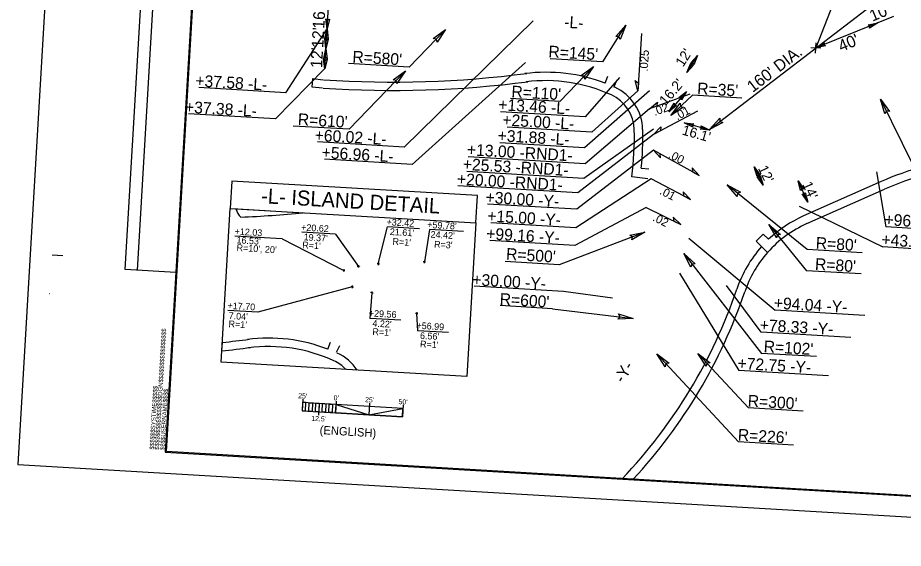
# Model space of a CAD drawing. Extents: x 2011491 to 2012372, y 444688 to 445287.
# Drawn here: x 2011491 to 2012020, y 444688 to 445005 of the extents above; entities that cross this region are included whole.
import ezdxf

# ---------------------------------------------------------------- set-up
doc = ezdxf.new("R2010")
doc.units = 0
for name, color, linetype in [('Old_Level_1', 7, 'Continuous'), ('Old_Level_10', 7, 'Continuous'), ('Prop Conc 5in Monolithic Keyed In Island', 7, 'Continuous'), ('Prop Dimension', 7, 'Continuous'), ('Prop Dimension Text', 7, 'Continuous'), ('Prop PHM English Scale CELL', 7, 'Continuous'), ('Prop Shade Medium', 7, 'Continuous'), ('Prop Superelevation  Arrow CELL', 7, 'Continuous'), ('Prop Superelevation Label', 7, 'Continuous'), ('Prop Terminator CELL', 7, 'Continuous'), ('Sheet Block Revision CELL', 7, 'Continuous'), ('Sheet Block System Information CELL', 7, 'Continuous'), ('Sheet Clip Boundary CELL', 7, 'Continuous'), ('Sheet Plan And Profile CELL', 7, 'Continuous'), ('Sheet Plot Border Outside CELL', 7, 'Continuous')]:
    doc.layers.add(name, color=color, linetype=linetype)

msp = doc.modelspace()

# ---------------------------------------------------------------- linework, layer by layer
at = {"layer": 'Old_Level_1'}
for points in [[(2011617.92, 444891.33), (2011764.48, 444882.69), (2011765.45, 444899.02), (2011618.88, 444907.66)], [(2011617.92, 444891.33), (2011764.48, 444882.69), (2011759.08, 444790.99), (2011612.52, 444799.63)]]:
    msp.add_lwpolyline(points, close=True, dxfattribs=at)
at = {"layer": 'Prop Conc 5in Monolithic Keyed In Island'}
msp.add_arc((2011549.01, 445418.55), 579.25, 266.1491, 266.16124, dxfattribs=at)
at = {"layer": 'Prop Dimension'}
for p, q in [((2011996.65, 445061.65), (2011967.46, 444987.16)), ((2011903.98, 444938.48), (2012030.95, 445035.85)), ((2011675.75, 444998.63), (2011676.73, 445015.19)), ((2012013.8, 445005.94), (2012004.54, 445002.19)), ((2011798.68, 445003.43), (2011721.67, 444928.02)), ((2011840.43, 444978.9), (2011854.11, 445000.81)), ((2012004.54, 445002.19), (2011967.46, 444987.16)), ((2011651.03, 444960.47), (2011675.75, 444998.63)), ((2011675.04, 444986.65), (2011675.75, 444998.63)), ((2011746.5, 444998.19), (2011724.82, 444975.71)), ((2011967.29, 444984.17), (2011967.64, 444990.16)), ((2011674.34, 444974.67), (2011675.04, 444986.65)), ((2011970.46, 444986.99), (2011964.47, 444987.34)), ((2011840.43, 444978.9), (2011808.95, 444980.75)), ((2011890.53, 444972.51), (2011896.92, 444982.66)), ((2011674.14, 444974.68), (2011644.84, 444944.79)), ((2011724.82, 444975.71), (2011688.49, 444977.85)), ((2011794.15, 444978.45), (2011726.51, 444917.66)), ((2011834.76, 444976.08), (2011814.64, 444955.22)), ((2011722.49, 444973.49), (2011688.82, 444938.59)), ((2011850.22, 444969.6), (2011829.74, 444946.05)), ((2011651.03, 444960.47), (2011599.09, 444963.53)), ((2011868.19, 444961.53), (2011829.33, 444927.55)), ((2011861.31, 444961.57), (2011833.82, 444936.82)), ((2011890.38, 444961.28), (2011879.81, 444948.99)), ((2011880.92, 444946.77), (2011893.91, 444958.96)), ((2011923.37, 444957.23), (2011893.91, 444958.96)), ((2011814.64, 444955.22), (2011785.17, 444956.96)), ((2012006.14, 444956.68), (2012035.03, 444897.56)), ((2011644.84, 444944.79), (2011592.9, 444947.85)), ((2011829.74, 444946.05), (2011779.22, 444949.03)), ((2011868.12, 444950.82), (2011829.79, 444918.06)), ((2011904.31, 444938.05), (2011888.8, 444942.42)), ((2011688.82, 444938.59), (2011655.42, 444940.56)), ((2011833.82, 444936.82), (2011783.31, 444939.8)), ((2011870.62, 444938.63), (2011829, 444909.26)), ((2011870.67, 444935.45), (2011825.4, 444900.72)), ((2011721.67, 444928.02), (2011670.02, 444931.06)), ((2011829.33, 444927.55), (2011778.81, 444930.53)), ((2011870.53, 444926.22), (2011824.82, 444890.83)), ((2011829.79, 444918.06), (2011760.01, 444922.17)), ((2011726.51, 444917.66), (2011674.18, 444920.74)), ((2011930.73, 444916.1), (2011936.05, 444905.34)), ((2011829, 444909.26), (2011759.22, 444913.37)), ((2012003.79, 444913.3), (2012009.29, 444880.37)), ((2011869.14, 444909.05), (2011824.17, 444879.83)), ((2011962.39, 444866.78), (2011914.5, 444905.43)), ((2011962.66, 444895.05), (2011956.98, 444907.85)), ((2011825.4, 444900.72), (2011753.72, 444904.94)), ((2011824.82, 444890.83), (2011771.59, 444893.97)), ((2011866.25, 444891.98), (2011823.55, 444869.21)), ((2011957.54, 444892.79), (2012007.49, 444868.35)), ((2011706.31, 444858.22), (2011711.7, 444880.35)), ((2011730.83, 444879.22), (2011711.7, 444880.35)), ((2011736.82, 444878.7), (2011733.79, 444859.42)), ((2011757.08, 444877.51), (2011736.82, 444878.7)), ((2011824.17, 444879.83), (2011773.51, 444882.82)), ((2011939.51, 444881.73), (2011961.92, 444854.17)), ((2012080.44, 444876.17), (2012009.29, 444880.37)), ((2011648.82, 444873.17), (2011620.69, 444874.83)), ((2011680.8, 444875.96), (2011660.71, 444877.14)), ((2011680.8, 444875.96), (2011694.39, 444856.73)), ((2011865.49, 444877.22), (2011814.3, 444857.74)), ((2011891.74, 444873.57), (2011943.2, 444830.62)), ((2011648.82, 444873.17), (2011685.66, 444854.35)), ((2011823.55, 444869.21), (2011772.88, 444872.19)), ((2012061.63, 444865.15), (2012007.49, 444868.35)), ((2011888.63, 444864.37), (2011935.15, 444804.76)), ((2011995.08, 444864.86), (2011962.39, 444866.78)), ((2011814.3, 444857.74), (2011782.01, 444859.64)), ((2011886.03, 444852.69), (2011921.55, 444794.61)), ((2011994.61, 444852.24), (2011961.92, 444854.17)), ((2011690.76, 444844.55), (2011634.44, 444829.39)), ((2011816.92, 444841.71), (2011763.49, 444844.86)), ((2011846.14, 444837.85), (2011816.92, 444841.71)), ((2011934.79, 444817.44), (2011914.18, 444845.27)), ((2011702.44, 444841.03), (2011701.2, 444825.7)), ((2011810.36, 444831.48), (2011779.09, 444833.32)), ((2011810.36, 444831.48), (2011858.52, 444825.7)), ((2011634.44, 444829.39), (2011616.47, 444830.45)), ((2011719.82, 444824.6), (2011701.2, 444825.7)), ((2011729.18, 444828.66), (2011729.62, 444818.35)), ((2011996.74, 444827.46), (2011943.2, 444830.62)), ((2011748.24, 444817.25), (2011729.62, 444818.35)), ((2011988.33, 444814.29), (2011934.79, 444817.44)), ((2011927.3, 444772.21), (2011897.1, 444804.77)), ((2011967.84, 444802.83), (2011935.15, 444804.76)), ((2011921.39, 444751.9), (2011872.61, 444804.48)), ((2011975.09, 444791.45), (2011921.55, 444794.61)), ((2011959.99, 444770.29), (2011927.3, 444772.21)), ((2011954.08, 444749.97), (2011921.39, 444751.9))]:
    msp.add_line(p, q, dxfattribs=at)
at = {"layer": 'Prop Dimension Text'}
for p, q in [((2011694.43, 444857.48), (2011694.35, 444855.98)), ((2011706.31, 444858.22), (2011705.56, 444858.27)), ((2011706.35, 444858.97), (2011706.26, 444857.47)), ((2011706.31, 444858.22), (2011707.05, 444858.18)), ((2011733.79, 444859.42), (2011733.04, 444859.46)), ((2011733.83, 444860.17), (2011733.74, 444858.67)), ((2011733.79, 444859.42), (2011734.54, 444859.38)), ((2011685.66, 444854.35), (2011684.91, 444854.4)), ((2011685.71, 444855.1), (2011685.62, 444853.6)), ((2011685.66, 444854.35), (2011686.41, 444854.31)), ((2011694.39, 444856.73), (2011693.64, 444856.77)), ((2011694.39, 444856.73), (2011695.14, 444856.68)), ((2011690.76, 444844.55), (2011690.01, 444844.59)), ((2011690.8, 444845.3), (2011690.71, 444843.8)), ((2011690.76, 444844.55), (2011691.5, 444844.5)), ((2011702.48, 444841.78), (2011702.39, 444840.28)), ((2011702.44, 444841.03), (2011701.69, 444841.08)), ((2011702.44, 444841.03), (2011703.19, 444840.99)), ((2011729.18, 444828.66), (2011728.43, 444828.7)), ((2011729.23, 444829.41), (2011729.14, 444827.91)), ((2011729.18, 444828.66), (2011729.93, 444828.61))]:
    msp.add_line(p, q, dxfattribs=at)
at = {"layer": 'Prop PHM English Scale CELL'}
for p, q in [((2011661.21, 444777.5), (2011660.8, 444770.51)), ((2011661.09, 444775.5), (2011660.8, 444770.51)), ((2011720.99, 444771.97), (2011661.09, 444775.5)), ((2011661.23, 444777.9), (2011661.23, 444777.9)), ((2011671.08, 444774.91), (2011670.66, 444767.92)), ((2011681.18, 444776.32), (2011680.76, 444769.29)), ((2011701.14, 444775.14), (2011700.73, 444768.15)), ((2011701.16, 444775.54), (2011701.16, 444775.54)), ((2011721.11, 444773.97), (2011720.69, 444766.98)), ((2011721.13, 444774.36), (2011721.13, 444774.36)), ((2011660.8, 444770.51), (2011720.69, 444766.98)), ((2011720.69, 444766.98), (2011720.99, 444771.97))]:
    msp.add_line(p, q, dxfattribs=at)
for points in [[(2011663.09, 444775.38), (2011661.09, 444775.5), (2011660.8, 444770.51), (2011662.8, 444770.39)], [(2011665.09, 444775.26), (2011667.08, 444775.15), (2011666.79, 444770.16), (2011664.79, 444770.27)], [(2011669.08, 444775.03), (2011671.08, 444774.91), (2011670.78, 444769.92), (2011668.78, 444770.04)], [(2011673.07, 444774.79), (2011675.07, 444774.68), (2011674.77, 444769.68), (2011672.78, 444769.8)], [(2011677.07, 444774.56), (2011679.06, 444774.44), (2011678.77, 444769.45), (2011676.77, 444769.57)], [(2011681.06, 444774.32), (2011700.73, 444768.11), (2011680.76, 444769.29)], [(2011700.73, 444768.11), (2011720.88, 444771.89), (2011720.69, 444766.98)]]:
    msp.add_lwpolyline(points, close=True, dxfattribs=at)
at = {"layer": 'Prop Shade Medium'}
for p, q in [((2011666.83, 444963.86), (2011667.18, 444968.85)), ((2011667.18, 444968.85), (2011673.48, 444968.21)), ((2011841.78, 444966.11), (2011843.39, 444970.32)), ((2011672.98, 444963.24), (2011666.83, 444963.86)), ((2011848.75, 444968.02), (2011846.83, 444964)), ((2011863.3, 444915.44), (2011867.78, 444915.01)), ((2011867.12, 444909.05), (2011857.7, 444910.24)), ((2012006.43, 444907.36), (2011960.17, 444886.84)), ((2011962.2, 444882.27), (2012008.46, 444902.79)), ((2011622.37, 444891.07), (2011661.46, 444888.76)), ((2011936.09, 444876.05), (2011931.91, 444871.74)), ((2011939.32, 444872.92), (2011936.09, 444876.05)), ((2011931.91, 444871.74), (2011938.74, 444865.13)), ((2011938.74, 444865.13), (2011935.15, 444868.61)), ((2011695.38, 444856.85), (2011695.38, 444856.85)), ((2011612.91, 444806.29), (2011613.21, 444811.35)), ((2011676.08, 444807.34), (2011677.69, 444811.56)), ((2011683.05, 444809.26), (2011681.13, 444805.24))]:
    msp.add_line(p, q, dxfattribs=at)
for centre, radius, start, end in [((2011715.1, 445583.3), 616.5, 266.1491, 277.4453), ((2011806.45, 444874.16), 98.5, 68.9825, 97.3398), ((2011715.1, 445583.3), 621.5, 266.1491, 277.4453), ((2011806.45, 444874.16), 93.5, 65.3598, 97.3398), ((2011806.45, 444874.16), 98.5, 65.3598, 65.7971), ((2011835.63, 444937.79), 28.5, 1.3736, 65.3598), ((2011835.63, 444937.79), 23.5, 1.3736, 65.3598), ((2011670.68, 444933.83), 188.5, 352.81, 1.3736), ((2011670.68, 444933.83), 193.5, 354.5462, 1.3736), ((2012078.79, 444744.18), 178.5, 105.3785, 113.9163), ((2012078.79, 444744.18), 173.5, 105.3785, 113.9163), ((2011596.57, 445544.06), 653.5, 272.17018, 272.26241), ((2011633.66, 444895.11), 13, 198.3383, 223.6709), ((2011596.57, 445544.06), 658.5, 272.40941, 275.65522), ((2011989.97, 444819.65), 73.5, 113.9163, 133.5582), ((2011989.97, 444819.65), 68.5, 113.9163, 138.4074), ((2011989.97, 444819.65), 73.5, 138.2363, 161.328), ((2011989.97, 444819.65), 68.5, 138.4074, 161.328), ((2011629.97, 444941.31), 306.5, 316.4201, 341.328), ((2011629.97, 444941.31), 311.5, 317.1922, 341.328), ((2011549.41, 445424.54), 616.5, 275.93991, 277.4453), ((2011640.75, 444715.4), 98.5, 68.9825, 97.3398), ((2011549.41, 445424.54), 621.5, 275.86433, 277.4453), ((2011640.75, 444715.4), 93.5, 65.3598, 97.3398), ((2011669.94, 444779.02), 28.5, 33.7314, 65.3598), ((2011669.94, 444779.02), 23.5, 43.65, 65.3598)]:
    msp.add_arc(centre, radius, start, end, dxfattribs=at)
at = {"layer": 'Prop Superelevation  Arrow CELL'}
for points in [[(2011861.31, 444961.57), (2011859.66, 444967.68), (2011861.58, 444966.19)], [(2011868.12, 444950.82), (2011873.06, 444954.76), (2011872.46, 444952.41)], [(2011870.67, 444935.45), (2011875.02, 444940.04), (2011874.75, 444937.63)], [(2011870.53, 444926.22), (2011874.82, 444921.56), (2011874.58, 444923.98)], [(2011897.95, 444911.04), (2011893.67, 444915.69), (2011893.91, 444913.28)], [(2011892.64, 444896.68), (2011888.26, 444901.24), (2011888.55, 444898.83)], [(2011886.83, 444881.71), (2011882.35, 444886.18), (2011882.69, 444883.78)]]:
    msp.add_lwpolyline(points, close=True, dxfattribs=at)
at = {"layer": 'Prop Superelevation Label'}
for p, q in [((2011863.33, 444995.85), (2011861.31, 444961.57)), ((2011892.33, 444959.68), (2011868.12, 444950.82)), ((2011896.9, 444949.46), (2011870.67, 444935.45)), ((2011897.95, 444911.04), (2011870.53, 444926.22)), ((2011892.64, 444896.68), (2011869.14, 444909.05)), ((2011866.25, 444891.98), (2011886.83, 444881.71))]:
    msp.add_line(p, q, dxfattribs=at)
at = {"layer": 'Prop Terminator CELL'}
for points in [[(2011677.1, 445004.41), (2011675.75, 444998.63), (2011675.06, 445004.56), (2011676.05, 445003.75)], [(2011848.03, 444993.99), (2011854.11, 445000.81), (2011850.67, 444992.28), (2011849.93, 444994.11)], [(2011998.74, 445000.92), (2012004.54, 445002.19), (2011999.48, 444999.01), (2011999.78, 445000.26)], [(2011674.4, 444992.85), (2011675.75, 444998.63), (2011676.44, 444992.69), (2011675.45, 444993.5)], [(2011739.13, 444992.79), (2011746.5, 444998.19), (2011741.37, 444990.56), (2011741.01, 444992.5)], [(2011676.39, 444992.43), (2011675.04, 444986.65), (2011674.35, 444992.58), (2011675.35, 444991.77)], [(2011973.26, 444988.43), (2011967.46, 444987.16), (2011972.53, 444990.34), (2011972.22, 444989.09)], [(2011673.69, 444980.87), (2011675.04, 444986.65), (2011675.74, 444980.71), (2011674.74, 444981.52)], [(2011675.69, 444980.45), (2011674.34, 444974.67), (2011673.65, 444980.6), (2011674.64, 444979.79)], [(2011892.95, 444978.25), (2011896.92, 444982.66), (2011894.67, 444977.13), (2011894.19, 444978.32)], [(2011827.4, 444970.68), (2011834.76, 444976.08), (2011829.63, 444968.46), (2011829.28, 444970.4)], [(2011894.5, 444976.92), (2011890.53, 444972.51), (2011892.78, 444978.04), (2011893.26, 444976.85)], [(2011715.13, 444968.09), (2011722.49, 444973.49), (2011717.36, 444965.87), (2011717.01, 444967.81)], [(2011885.8, 444957.5), (2011890.38, 444961.28), (2011887.33, 444956.14), (2011887.03, 444957.39)], [(2011884.39, 444952.77), (2011879.81, 444948.99), (2011882.86, 444954.13), (2011883.16, 444952.88)], [(2011888.54, 444951.8), (2011880.92, 444946.77), (2011886.42, 444954.13), (2011886.68, 444952.18)], [(2012008.7, 444947.91), (2012006.14, 444956.68), (2012011.56, 444949.25), (2012009.61, 444949.58)], [(2011894.16, 444939.85), (2011888.8, 444942.42), (2011894.75, 444941.81), (2011893.75, 444941.02)], [(2011912.07, 444942.73), (2011903.98, 444938.48), (2011910.19, 444945.26), (2011910.25, 444943.29)], [(2011898.96, 444940.62), (2011904.31, 444938.05), (2011898.37, 444938.65), (2011899.37, 444939.45)], [(2011932.42, 444910.41), (2011930.73, 444916.1), (2011934.27, 444911.29), (2011933.01, 444911.49)], [(2011934.36, 444911.03), (2011936.05, 444905.34), (2011932.51, 444910.15), (2011933.78, 444909.94)], [(2011920.53, 444898.57), (2011914.5, 444905.43), (2011922.55, 444900.99), (2011920.65, 444900.47)], [(2011958.43, 444902.1), (2011956.98, 444907.85), (2011960.32, 444902.9), (2011959.06, 444903.16)], [(2011961.21, 444900.81), (2011962.66, 444895.05), (2011959.32, 444900.01), (2011960.57, 444899.75)], [(2011943.99, 444873.77), (2011939.51, 444881.73), (2011946.46, 444875.72), (2011944.5, 444875.6)], [(2011856.52, 444875.47), (2011865.49, 444877.22), (2011857.6, 444872.5), (2011858.1, 444874.41)], [(2011892.95, 444856.33), (2011888.63, 444864.37), (2011895.46, 444858.22), (2011893.49, 444858.15)], [(2011849.77, 444828.31), (2011858.52, 444825.7), (2011849.35, 444825.19), (2011850.68, 444826.64)], [(2011902.08, 444797.12), (2011897.1, 444804.77), (2011904.43, 444799.22), (2011902.47, 444798.98)], [(2011877.6, 444796.83), (2011872.61, 444804.48), (2011879.94, 444798.93), (2011877.99, 444798.69)]]:
    msp.add_lwpolyline(points, close=True, dxfattribs=at)
at = {"layer": 'Sheet Block Revision CELL'}
msp.add_line((2011562.49, 444854.41), (2011585.75, 445249.04), dxfattribs=at)
msp.add_lwpolyline([(2011555.23, 444854.83), (2011578.49, 445249.47), (2011608.71, 445247.69), (2011585.45, 444853.05)], close=True, dxfattribs=at)
at = {"layer": 'Sheet Block System Information CELL'}
msp.add_line((2011579.13, 444745.74), (2011579.13, 444745.74), dxfattribs=at)
at = {"layer": 'Sheet Clip Boundary CELL'}
for points in [[(2012353.36, 445134.84), (2012253.51, 445140.73), (2012256.91, 445198.29), (2012157.05, 445204.18), (2012159.02, 445237.47), (2011610.02, 445269.83), (2011579.13, 444745.74), (2012327.83, 444701.6)], [(2011579.79, 444746.22), (2011610.64, 445269.52), (2012158.83, 445237.2), (2012156.87, 445204), (2012256.73, 445198.11), (2012253.34, 445140.51), (2012353.28, 445134.62), (2012327.76, 444701.71)]]:
    msp.add_lwpolyline(points, close=True, dxfattribs=at)
at = {"layer": 'Sheet Plan And Profile CELL'}
for p, q in [((2011511.7, 444863.66), (2011517.94, 444863.29)), ((2011579.13, 444745.74), (2011579.13, 444745.74)), ((2011579.13, 444745.74), (2011579.13, 444745.74)), ((2011579.13, 444745.74), (2011579.13, 444745.74)), ((2011579.13, 444745.74), (2011579.13, 444745.74)), ((2011579.13, 444745.74), (2011579.13, 444745.74))]:
    msp.add_line(p, q, dxfattribs=at)
msp.add_lwpolyline([(2012358.72, 445225.69), (2011610.02, 445269.83), (2011579.13, 444745.74), (2012327.83, 444701.6)], close=True, dxfattribs=at)
at = {"layer": 'Sheet Plot Border Outside CELL'}
msp.add_lwpolyline([(2011491.04, 444738.41), (2012339.57, 444688.39), (2012371.93, 445237.44), (2011523.41, 445287.46)], close=True, dxfattribs=at)

# ---------------------------------------------------------------- texts
at = {"layer": 'Old_Level_10'}
for s, p in [('+32.42', (2011711.13, 444881.36)), ('+12.03', (2011620.45, 444875.7)), ('+20.62', (2011660.15, 444878.16)), ("21.61'", (2011713.09, 444875.51)), ("+59.78'", (2011735.42, 444879.76)), ("16.53'", (2011621.56, 444870.53)), ("19.37'", (2011661.63, 444872.33)), ("R=1'", (2011714.69, 444869.66)), ("24.42'", (2011737.43, 444873.91)), ("R=10', 20'", (2011621.62, 444866.01)), ("R=1'", (2011660.82, 444867.59)), ("R=3'", (2011739.51, 444868.04)), ('+17.70', (2011616.21, 444831.42)), ("7.04'", (2011616.88, 444825.35)), ('+29.56', (2011700.57, 444826.89)), ("R=1'", (2011616.79, 444820.47)), ("4.22'", (2011702.69, 444820.81)), ('+56.99', (2011729.01, 444819.53)), ("R=1'", (2011702.69, 444815.85)), ("6.56'", (2011731.11, 444813.46)), ("R=1'", (2011731.11, 444808.49))]:
    msp.add_text(s, height=4, rotation=356.6264, dxfattribs=at).set_placement(p)
at = {"layer": 'Prop Dimension'}
for s, height, rotation, p in [('-L-', 7, 356.6264, (2011817.14, 444999.27)), ('-L- ISLAND DETAIL', 9, 356.6264, (2011636.15, 444894.53)), ('-Y- ', 7, 59.2088, (2011852.55, 444786.59))]:
    msp.add_text(s, height=height, rotation=rotation, dxfattribs=at).set_placement(p)
at = {"layer": 'Prop Dimension Text'}
for s, height, rotation, p in [("16.5'", 7, 87.057, (2011674.06, 444998.54)), ("10'", 7, 22.5868, (2012001.27, 445002.84)), ("12'", 7, 87.057, (2011673.46, 444987.05)), ("40'", 7, 22.5868, (2011982.65, 444984.74)), ("12'", 7, 87.057, (2011672.75, 444975.07)), ("R=580'", 7, 356.6264, (2011690.69, 444978.53)), ("R=145'", 7, 356.6264, (2011807.71, 444981.64)), ("12'", 6, 56.9341, (2011888.22, 444975.45)), ("160' DIA.", 7, 37.4838, (2011929.79, 444960.29)), ('+37.58 -L-', 7, 356.6264, (2011596.95, 444964.26)), ("16.2'", 6, 49.2916, (2011877.97, 444952.52)), ("R=110'", 7, 356.6264, (2011785.6, 444957.75)), ("R=35'", 7, 356.6264, (2011896.52, 444959.62)), ('+37.38 -L-', 7, 356.6264, (2011590.76, 444948.58)), ('+13.46 -L-', 7, 356.6264, (2011777.81, 444950.03)), ("R=610'", 7, 356.6264, (2011658.11, 444941.21)), ('+25.00 -L-', 7, 356.6264, (2011780.22, 444940.9)), ('+60.02 -L-', 7, 356.6264, (2011668.17, 444931.77)), ('+31.88 -L-', 7, 356.6264, (2011777.4, 444931.53)), ("16.1'", 6, 344.1936, (2011887.19, 444935.58)), ('+56.96 -L-', 7, 356.6264, (2011672.34, 444921.45)), ('+13.00 -RND1-', 7, 356.6264, (2011759.06, 444923.15)), ('+25.53 -RND1-', 7, 356.6264, (2011756.6, 444914.44)), ("12'", 6, 296.3467, (2011932.79, 444915.33)), ('+20.00 -RND1-', 7, 356.6264, (2011753.11, 444905.58)), ("14'", 6, 293.9163, (2011959.31, 444905.83)), ('+30.00 -Y-', 7, 356.6264, (2011770.2, 444894.65)), ('+15.00 -Y-', 7, 356.6264, (2011771.23, 444883.56)), ('+96.86 -RND1-', 7, 356.6264, (2012008.34, 444881.35)), ('+99.16 -Y-', 7, 356.6264, (2011770.6, 444872.93)), ("R=80'", 7, 356.6264, (2011967.31, 444867.34)), ('+43.89 -Y-', 7, 356.6264, (2012006.54, 444869.33)), ("R=500'", 7, 356.6264, (2011782.43, 444860.76)), ("R=80'", 7, 356.6264, (2011966.84, 444854.73)), ('+30.00 -Y-', 7, 356.6264, (2011762.3, 444845.53)), ("R=600'", 7, 356.6264, (2011778.63, 444833.84)), ('+94.04 -Y-', 7, 356.6264, (2011942.26, 444831.52)), ('+78.33 -Y-', 7, 356.6264, (2011933.86, 444818.35)), ("R=102'", 7, 356.6264, (2011936.22, 444805.55)), ('+72.75 -Y-', 7, 356.6264, (2011920.61, 444795.51)), ("R=300'", 7, 356.6264, (2011926.7, 444773.1)), ("R=226'", 7, 356.6264, (2011920.78, 444752.78))]:
    msp.add_text(s, height=height, rotation=rotation, dxfattribs=at).set_placement(p)
at = {"layer": 'Prop PHM English Scale CELL'}
for s, height, p in [("25'", 3, (2011658.39, 444778.06)), ("0'", 3, (2011679.54, 444776.82)), ("25'", 3, (2011698.32, 444775.71)), ("50'", 3, (2011718.29, 444774.53)), ("12.5'", 3, (2011666.19, 444764.55)), ('(ENGLISH)', 5, (2011671.17, 444756.63))]:
    msp.add_text(s, height=height, rotation=356.6264, dxfattribs=at).set_placement(p)
at = {"layer": 'Prop Superelevation Label'}
for s, rotation, p in [('.025', 86.6264, (2011867.15, 444972.94)), ('.02', 20.0943, (2011871.35, 444946.56)), ('.01', 28.1157, (2011884.76, 444943.88)), ('.00', 332.4532, (2011879.03, 444921.96)), ('.01', 332.4532, (2011873.84, 444900.2)), ('.02', 333.4877, (2011869.68, 444884.29))]:
    msp.add_text(s, height=5, rotation=rotation, dxfattribs=at).set_placement(p)
at = {"layer": 'Sheet Block System Information CELL'}
for s, p in [('$$$$$$$$$$$$$$$$DGN$$$$$$$$$$$$$$$$', (2011575.38, 444747.14)), ('$$$$$$SYSTIME$$$$$', (2011572.36, 444747.32)), ('$$$$USERNAME$$$$', (2011578.66, 444746.95))]:
    msp.add_text(s, height=2.625, rotation=86.6264, dxfattribs=at).set_placement(p)

doc.saveas('drawing.dxf')
